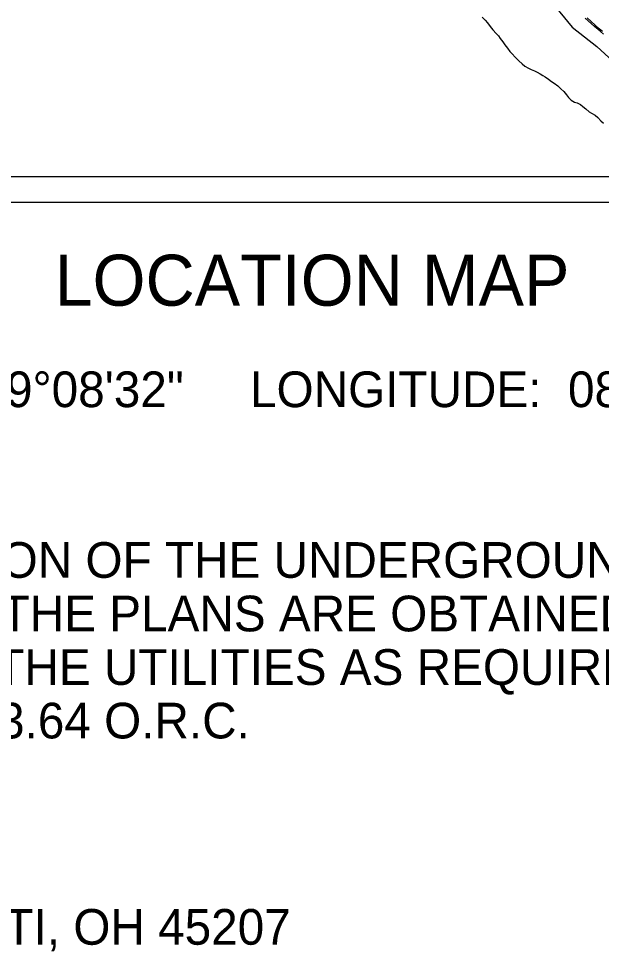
# Model space of a CAD drawing. Extents: x 0 to 43.4, y -8.1 to 22.
# Drawn here: x 4.286 to 6.573, y 11.061 to 14.72 of the extents above; entities that cross this region are included whole.
import ezdxf

# ---------------------------------------------------------------- set-up
doc = ezdxf.new("R2010")
doc.units = 0
for name, color, linetype in [('GM_X_Corporation', 7, 'Continuous'), ('GM_X_Major_River', 7, 'Continuous'), ('SH_Data', 7, 'Continuous'), ('SH_Text', 7, 'Continuous')]:
    doc.layers.add(name, color=color, linetype=linetype)

msp = doc.modelspace()

# ---------------------------------------------------------------- linework, layer by layer
at = {"layer": 'GM_X_Corporation'}
for points in [[(6.3804, 14.7818), (6.459, 14.6859), (6.5555, 14.6108), (6.6505, 14.5225), (6.7211, 14.4258), (6.8169, 14.3303), (6.9122, 14.3239), (7.0079, 14.2916), (7.1832, 14.2131), (7.3804, 14.1373), (7.4779, 14.1131), (7.5747, 14.1032), (7.7675, 14.1127), (7.989, 14.1), (8.1323, 14.1), (8.26, 14.1066), (8.4573, 14.1578), (8.5559, 14.198), (8.6538, 14.2731), (8.7491, 14.3326), (8.8466, 14.3678), (8.9, 14.3814), (8.9, 20.9)], [(6.3804, 14.7818), (6.459, 14.6859), (6.5555, 14.6108), (6.6505, 14.5225), (6.7211, 14.4258), (6.8169, 14.3303), (6.9122, 14.3239), (7.0079, 14.2916), (7.1832, 14.2131), (7.3804, 14.1373), (7.4779, 14.1131), (7.5747, 14.1032), (7.7675, 14.1127), (7.989, 14.1), (8.1323, 14.1), (8.26, 14.1066), (8.4573, 14.1578), (8.5559, 14.198), (8.6538, 14.2731), (8.7491, 14.3326), (8.8466, 14.3678), (8.9, 14.3814), (8.9, 17.1765)], [(6.3804, 14.7818), (6.459, 14.6859), (6.5555, 14.6108), (6.6505, 14.5225), (6.7211, 14.4258), (6.8169, 14.3303), (6.9122, 14.3239), (7.0079, 14.2916), (7.1832, 14.2131), (7.3804, 14.1373), (7.4779, 14.1131), (7.5747, 14.1032), (7.7675, 14.1127), (7.989, 14.1), (8.1323, 14.1), (8.26, 14.1066), (8.3976, 14.1356), (8.4633, 14.158), (8.5559, 14.198), (8.6538, 14.2731), (8.7491, 14.3326), (8.8466, 14.3678), (8.9, 14.3814), (8.9, 14.7281)], [(6.5772, 14.6697), (6.5641, 14.6791), (6.549, 14.6947), (6.5319, 14.7095), (6.5179, 14.7231)]]:
    msp.add_lwpolyline(points, dxfattribs=at)
at = {"layer": 'GM_X_Major_River'}
for points in [[(6.1056, 14.7261), (6.1164, 14.7138), (6.1257, 14.7034), (6.1369, 14.6892), (6.1477, 14.6754), (6.1604, 14.6615), (6.1689, 14.6519), (6.1764, 14.6419), (6.1864, 14.6284), (6.1946, 14.6165), (6.2046, 14.6039), (6.2135, 14.5912), (6.2232, 14.5812), (6.2344, 14.5685), (6.2486, 14.5546), (6.2624, 14.5422), (6.2722, 14.5337), (6.2868, 14.5251), (6.297, 14.5204), (6.3105, 14.5145), (6.3211, 14.5094), (6.3331, 14.5032), (6.3429, 14.4973), (6.353, 14.4911), (6.3658, 14.4821), (6.3774, 14.4736), (6.3879, 14.4662), (6.4022, 14.4558), (6.4134, 14.445), (6.4261, 14.4334), (6.4369, 14.4203), (6.4447, 14.4107), (6.454, 14.4003), (6.4672, 14.3921), (6.4782, 14.3893), (6.4906, 14.3826), (6.5003, 14.3757), (6.5123, 14.3656), (6.525, 14.3544), (6.5348, 14.3489), (6.5491, 14.3407), (6.5592, 14.3322), (6.5715, 14.3191)], [(6.5821, 14.6593), (6.5698, 14.669), (6.56, 14.6771), (6.5462, 14.6891), (6.5346, 14.6999), (6.5219, 14.7115), (6.5099, 14.7212)], [(6.5715, 14.3191), (6.5812, 14.3099)]]:
    msp.add_lwpolyline(points, dxfattribs=at)
at = {"layer": 'SH_Data'}
for p, q in [((2.1, 14.1), (8.9, 14.1)), ((2, 14), (9, 14))]:
    msp.add_line(p, q, dxfattribs=at)

# ---------------------------------------------------------------- texts
at = {"layer": 'SH_Text'}
for s, height, p in [('LOCATION MAP', 0.2, (4.4269, 13.5937)), ('LATITUDE:  39°08\'32"     LONGITUDE:  084°37\'51"', 0.14, (3.071, 13.1958)), ('THE LOCATION OF THE UNDERGROUND UTILITIES', 0.14, (3.1124, 12.5264)), ('SHOWN ON THE PLANS ARE OBTAINED FROM THE', 0.14, (3.1124, 12.3164)), ('OWNER OF THE UTILITIES AS REQUIRED BY', 0.14, (3.1124, 12.1064)), ('SECTION 153.64 O.R.C.', 0.14, (3.1124, 11.8964)), ('2010 DANA AVE, CINCINNATI, OH 45207', 0.14, (1.8057, 11.0873))]:
    msp.add_text(s, height=height, dxfattribs=at).set_placement(p)

doc.saveas('drawing.dxf')
